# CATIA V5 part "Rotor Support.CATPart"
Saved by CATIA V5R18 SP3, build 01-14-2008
Part number: Table Center Axis01
Bounding box of the stored display mesh (mm): x -50 to 50, y -47 to 0, z -49.993 to 49.993
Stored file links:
  E:\#00 CATIA V5 Movie\#03 CATIA V5 Data\#07 KIN\Balance Unit (1)\Rotor Support.CATPart
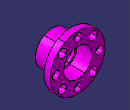
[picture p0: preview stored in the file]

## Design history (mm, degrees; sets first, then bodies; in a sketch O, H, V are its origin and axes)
Body1 (main body)
  Sketch1 on yz-plane, origin (0, 0, 0), H (0, 1, 0), V (0, 0, 1)
    line L1 (-47, 26) -> (-32, 26)
    line L2 (-32, 26) -> (-32, 22.5)
    line L3 (-32, 22.5) -> (-27.118, 22.5)
    line L4 (-27.118, 22.5) -> (-27.118, 26)
    point P5 (-27.118, 26)
    line L5 (-27.118, 26) -> (0, 26)
    point P6 (0, 26)
    line L6 (0, 26) -> (0, 50)
    line L7 (0, 50) -> (-12, 50)
    line L8 (-12, 50) -> (-12, 31)
    line L9 (-12, 31) -> (-47, 31)
    line L10 (-47, 31) -> (-47, 26)
    distance L1 H = 26
    distance L3 H = 22.5
    distance L10 L6 = 47
    distance L10 L2 = 15
    distance L2 L4 = 4.882
    distance L8 L6 = 12
    distance L7 H = 50
    distance L9 H = 31
    horizontal: L1 H, L3 H, L5 H, L7 H, L9 H
    vertical: L2 V, L4 V, L6 V, L8 V, L10 V
    coincidence: P5 L1, P6 V
  Shaft1: profile Sketch1, axis Sketch1.H, angle 360
  Sketch2 on face of Shaft1 from Sketch1.L6, origin (-28.2843, 0, 28.2843), H (1, 0, 0), V (0, 0, -1)
    point P1 (0, 0)
    reference projected point E1 (0, 0) from Sketch3.P5
    coincidence: E1 P1
  Hole1: placed by Sketch2, at (-28.2843, 0, 28.2843) direction (0, -1, 0), diameter 15, through (limit type 6)
  Sketch3 on face of Shaft1 from Sketch1.L6, origin (0, 0, 0), H (-1, 0, 0), V (0, 0, 1)
    construction line L1 (38.4731, 38.4731) -> (-40.8173, -40.8173)
    construction line L2 (-52.4162, 52.4162) -> (46.8154, -46.8154)
    construction circle A1 centre (0, 0) radius 40
    point P5 (28.2843, 28.2843)
    point P6 (28.2843, -28.2843)
    point P7 (-28.2843, -28.2843)
    point P8 (-28.2843, 28.2843)
    angle L2 H = 45
    angle L1 H = 45
    radius A1 = 40
    coincidence: L1 O, L2 O, P5 A1, P5 L1, P6 A1, P6 L2, P7 A1, P7 L1, P8 A1, P8 L2
  UserPattern1: of Hole1, copies 4, at the points of Sketch3
  Sketch4 on face of Shaft1 from Sketch1.L6, origin (0, 0, 40), H (1, 0, 0), V (0, 0, -1)
    point P1 (0, 0)
    reference projected point E1 (0, 0) from Sketch5.P1
    coincidence: E1 P1
  Hole2: placed by Sketch4, at (0, 0, 40) direction (0, -1, 0), diameter 9, through (limit type 6), counterbore diameter 14, counterbore depth 8
  CircPattern1: of Hole2, instances 4, angular step 90, axis from zx-plane
  Sketch5 on face of Shaft1 from Sketch1.L6, origin (0, 0, 0), H (-1, 0, 0), V (0, 0, 1)
    construction circle A1 centre (0, 0) radius 40
    point P1 (0, 40)
    radius A1 = 40
    coincidence: P1 A1, P1 V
